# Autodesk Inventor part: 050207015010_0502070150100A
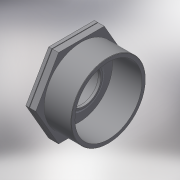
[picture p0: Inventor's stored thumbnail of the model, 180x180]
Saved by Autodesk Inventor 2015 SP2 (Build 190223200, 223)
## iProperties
Created: 2017-05
Part Number: 050207015010_0502070150100A
Material: Generic
Description: PLASSON REDUCING BUSHING 1.1/2"-1"
Document SubType Name: Modeling
Designer: KIM
Density: 1 g/cm^3
Appearance: Default
Author: KIM
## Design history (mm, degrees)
derived "050207.ipt"
feature "Solid1::050207.ipt"
tag "TaggingFeature1"
body "Solid1"
other parameters: "d1" = 47.803, "d5" = 21, "d8" = 0.37, "d12" = 0, "d15" = 37, "d19" = 0, "d30" = 9.25, "d31" = 4.625, "d33" = 30.291, "d34" = 43.0227, "d36" = 2.5, "d37" = 36.3492, "d38" = 24.42, "d39" = 27.2619, "d40" = 2.1, "d41" = 0, "H_" = 37, "R_" = 47.803, "l_2" = 21, "Rp_" = 30.291
